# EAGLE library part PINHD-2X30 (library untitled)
PIN HEADER
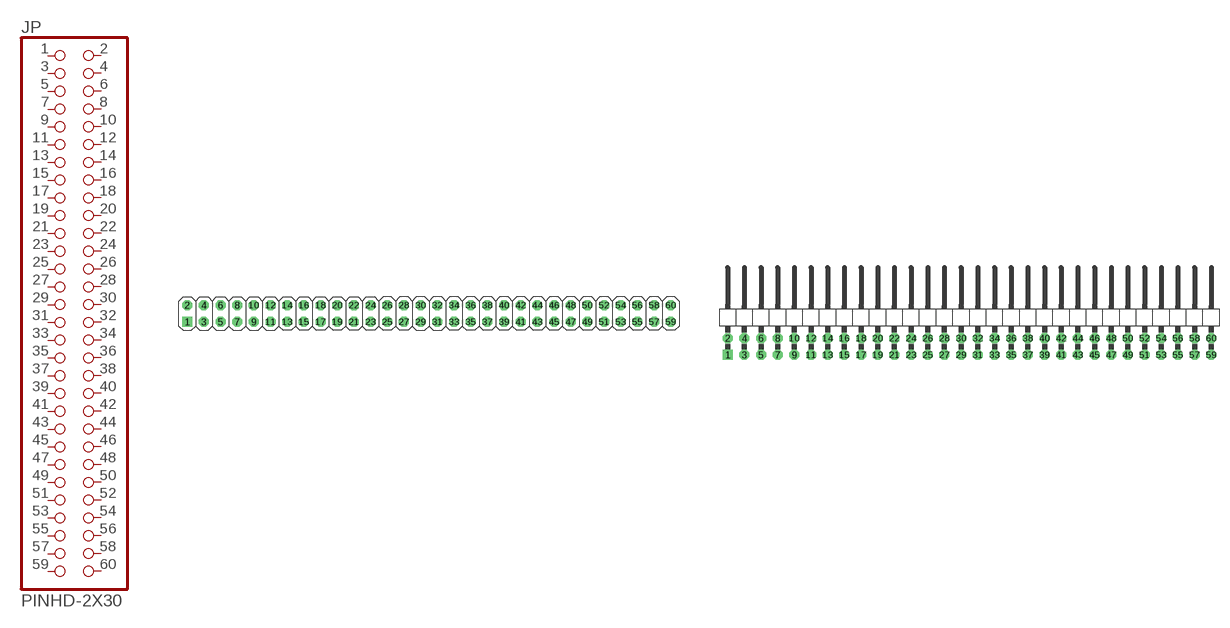
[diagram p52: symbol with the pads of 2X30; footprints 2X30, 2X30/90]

Designator prefix JP

## PINHD-2X30_2.54  [2X30]
1  1  pas
2  2  pas
3  3  pas
4  4  pas
5  5  pas
6  6  pas
7  7  pas
8  8  pas
9  9  pas
10  10  pas
11  11  pas
12  12  pas
13  13  pas
14  14  pas
15  15  pas
16  16  pas
17  17  pas
18  18  pas
19  19  pas
20  20  pas
21  21  pas
22  22  pas
23  23  pas
24  24  pas
25  25  pas
26  26  pas
27  27  pas
28  28  pas
29  29  pas
30  30  pas
31  31  pas
32  32  pas
33  33  pas
34  34  pas
35  35  pas
36  36  pas
37  37  pas
38  38  pas
39  39  pas
40  40  pas
41  41  pas
42  42  pas
43  43  pas
44  44  pas
45  45  pas
46  46  pas
47  47  pas
48  48  pas
49  49  pas
50  50  pas
51  51  pas
52  52  pas
53  53  pas
54  54  pas
55  55  pas
56  56  pas
57  57  pas
58  58  pas
59  59  pas
60  60  pas

## PINHD-2X30_2.54-90°  [2X30/90]
Pads as for 2X30

## PINHD-2X30_2.00  [2X30M]
Pads as for 2X30

## PINHD-2X30_2.54-SMD  [2X30SMD]
Pads as for 2X30

## PINHD-2X30_2.54-SMD-90°  [2X30SMD/90]
Pads as for 2X30

## Footprint 2X30 (pad centres in mm)
PIN HEADER - 2.54
drill 1.016 square: 1 -38.1,-1.27
drill 1.016 octagon: 2 -38.1,1.27; 3 -35.56,-1.27; 4 -35.56,1.27; 5 -33.02,-1.27; 6 -33.02,1.27; 7 -30.48,-1.27; 8 -30.48,1.27; 9 -27.94,-1.27; 10 -27.94,1.27; 11 -25.4,-1.27; 12 -25.4,1.27; 13 -22.86,-1.27; 14 -22.86,1.27; 15 -20.32,-1.27; 16 -20.32,1.27; 17 -17.78,-1.27; 18 -17.78,1.27; 19 -15.24,-1.27; 20 -15.24,1.27; 21 -12.7,-1.27; 22 -12.7,1.27; 23 -10.16,-1.27; 24 -10.16,1.27; 25 -7.62,-1.27; 26 -7.62,1.27; 27 -5.08,-1.27; 28 -5.08,1.27; 29 -2.54,-1.27; 30 -2.54,1.27; 31 0,-1.27; 32 0,1.27; 33 2.54,-1.27; 34 2.54,1.27; 35 5.08,-1.27; 36 5.08,1.27; 37 7.62,-1.27; 38 7.62,1.27; 39 10.16,-1.27; 40 10.16,1.27; 41 12.7,-1.27; 42 12.7,1.27; 43 15.24,-1.27; 44 15.24,1.27; 45 17.78,-1.27; 46 17.78,1.27; 47 20.32,-1.27; 48 20.32,1.27; 49 22.86,-1.27; 50 22.86,1.27; 51 25.4,-1.27; 52 25.4,1.27; 53 27.94,-1.27; 54 27.94,1.27; 55 30.48,-1.27; 56 30.48,1.27; 57 33.02,-1.27; 58 33.02,1.27; 59 35.56,-1.27; 60 35.56,1.27

## Footprint 2X30/90 (pad centres in mm)
PIN HEADER - 2.54 90°
drill 1.016 square: 1 -24.13,-6.35
drill 1.016 octagon: 2 -24.13,-3.81; 3 -21.59,-6.35; 4 -21.59,-3.81; 5 -19.05,-6.35; 6 -19.05,-3.81; 7 -16.51,-6.35; 8 -16.51,-3.81; 9 -13.97,-6.35; 10 -13.97,-3.81; 11 -11.43,-6.35; 12 -11.43,-3.81; 13 -8.89,-6.35; 14 -8.89,-3.81; 15 -6.35,-6.35; 16 -6.35,-3.81; 17 -3.81,-6.35; 18 -3.81,-3.81; 19 -1.27,-6.35; 20 -1.27,-3.81; 21 1.27,-6.35; 22 1.27,-3.81; 23 3.81,-6.35; 24 3.81,-3.81; 25 6.35,-6.35; 26 6.35,-3.81; 27 8.89,-6.35; 28 8.89,-3.81; 29 11.43,-6.35; 30 11.43,-3.81; 31 13.97,-6.35; 32 13.97,-3.81; 33 16.51,-6.35; 34 16.51,-3.81; 35 19.05,-6.35; 36 19.05,-3.81; 37 21.59,-6.35; 38 21.59,-3.81; 39 24.13,-6.35; 40 24.13,-3.81; 41 26.67,-6.35; 42 26.67,-3.81; 43 29.21,-6.35; 44 29.21,-3.81; 45 31.75,-6.35; 46 31.75,-3.81; 47 34.29,-6.35; 48 34.29,-3.81; 49 36.83,-6.35; 50 36.83,-3.81; 51 39.37,-6.35; 52 39.37,-3.81; 53 41.91,-6.35; 54 41.91,-3.81; 55 44.45,-6.35; 56 44.45,-3.81; 57 46.99,-6.35; 58 46.99,-3.81; 59 49.53,-6.35; 60 49.53,-3.81

## Footprint 2X30M (pad centres in mm)
PIN HEADER - 2
drill 0.914 square: 1 -24,-1
drill 0.914 round: 2 -24,1; 3 -22,-1; 4 -22,1; 5 -20,-1; 6 -20,1; 7 -18,-1; 8 -18,1; 9 -16,-1; 10 -16,1; 11 -14,-1; 12 -14,1; 13 -12,-1; 14 -12,1; 15 -10,-1; 16 -10,1; 17 -8,-1; 18 -8,1; 19 -6,-1; 20 -6,1; 21 -4,-1; 22 -4,1; 23 -2,-1; 24 -2,1; 25 0,-1; 26 0,1; 27 2,-1; 28 2,1; 29 4,-1; 30 4,1; 31 6,-1; 32 6,1; 33 8,-1; 34 8,1; 35 10,-1; 36 10,1; 37 12,-1; 38 12,1; 39 14,-1; 40 14,1; 41 16,-1; 42 16,1; 43 18,-1; 44 18,1; 45 20,-1; 46 20,1; 47 22,-1; 48 22,1; 49 24,-1; 50 24,1; 51 26,-1; 52 26,1; 53 28,-1; 54 28,1; 55 30,-1; 56 30,1; 57 32,-1; 58 32,1; 59 34,-1; 60 34,1

## Footprint 2X30SMD (pad centres in mm)
PIN HEADER - 2.54 SMD
smd 1.016 x 3.302: 1 -1.27,-3.81; 2 -1.27,1.27; 3 1.27,-3.81; 4 1.27,1.27; 5 3.81,-3.81; 6 3.81,1.27; 7 6.35,-3.81; 8 6.35,1.27; 9 8.89,-3.81; 10 8.89,1.27; 11 11.43,-3.81; 12 11.43,1.27; 13 13.97,-3.81; 14 13.97,1.27; 15 16.51,-3.81; 16 16.51,1.27; 17 19.05,-3.81; 18 19.05,1.27; 19 21.59,-3.81; 20 21.59,1.27; 21 24.13,-3.81; 22 24.13,1.27; 23 26.67,-3.81; 24 26.67,1.27; 25 29.21,-3.81; 26 29.21,1.27; 27 31.75,-3.81; 28 31.75,1.27; 29 34.29,-3.81; 30 34.29,1.27; 31 36.83,-3.81; 32 36.83,1.27; 33 39.37,-3.81; 34 39.37,1.27; 35 41.91,-3.81; 36 41.91,1.27; 37 44.45,-3.81; 38 44.45,1.27; 39 46.99,-3.81; 40 46.99,1.27; 41 49.53,-3.81; 42 49.53,1.27; 43 52.07,-3.81; 44 52.07,1.27; 45 54.61,-3.81; 46 54.61,1.27; 47 57.15,-3.81; 48 57.15,1.27; 49 59.69,-3.81; 50 59.69,1.27; 51 62.23,-3.81; 52 62.23,1.27; 53 64.77,-3.81; 54 64.77,1.27; 55 67.31,-3.81; 56 67.31,1.27; 57 69.85,-3.81; 58 69.85,1.27; 59 72.39,-3.81; 60 72.39,1.27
